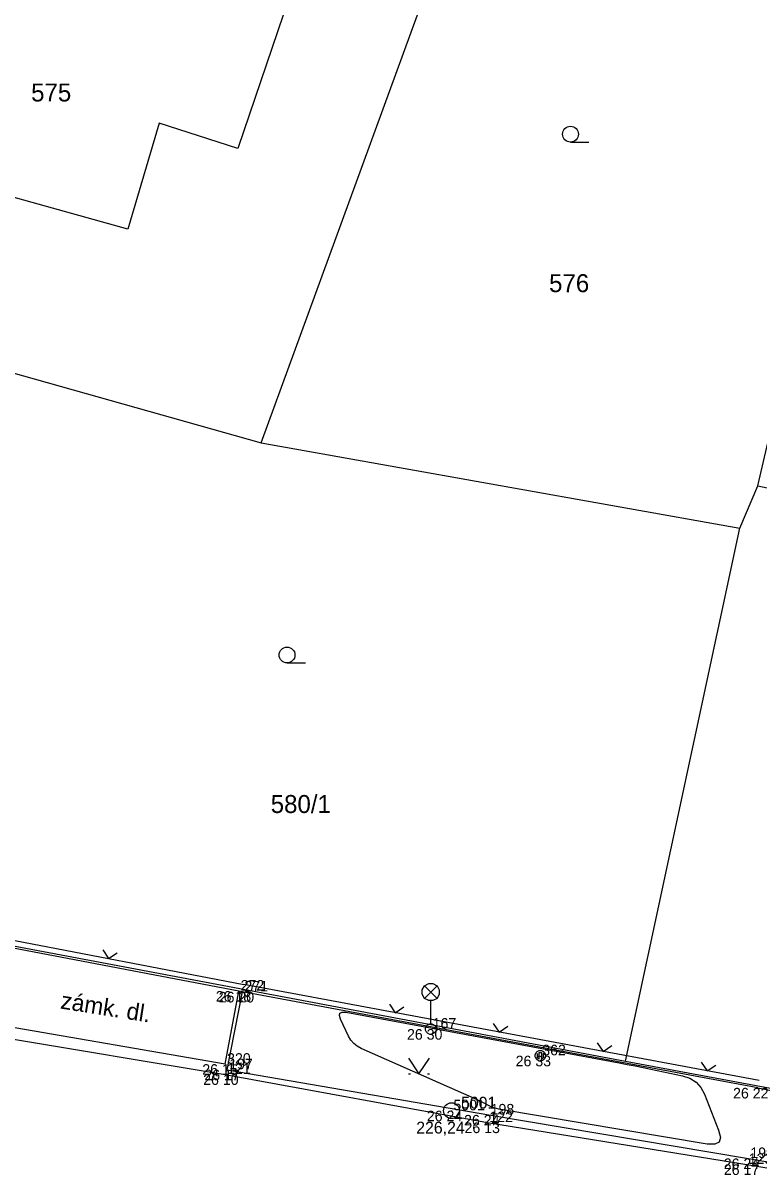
# Model space of a CAD drawing. Extents: x -702257 to -701487, y -1009871 to -1008841.
# Drawn here: x -701745.96 to -701728.56, y -1009385.88 to -1009358.61 of the extents above; entities that cross this region are included whole.
import ezdxf

# ---------------------------------------------------------------- set-up
doc = ezdxf.new("R2010")
doc.units = 0
for name, color, linetype in [('Ex_Minor Contours', 7, 'Continuous'), ('Z_bodove_pole', 7, 'Continuous'), ('Z_bodove_pole_cisla', 7, 'Continuous'), ('Z_bodove_pole_vysky', 7, 'Continuous'), ('Z_body', 7, 'Continuous'), ('Z_body_cisla', 7, 'Continuous'), ('Z_body_vysky_redukovane', 7, 'Continuous'), ('Z_katastr_cisla_pozemkova', 7, 'Continuous'), ('Z_katastr_cisla_stavebni', 7, 'Continuous'), ('Z_katastr_hranice', 7, 'Continuous'), ('Z_katastr_vnitrni_kresba', 7, 'Continuous'), ('Z_katastr_znacky_kultur', 7, 'Continuous'), ('Z_komunikace', 7, 'Continuous'), ('Z_obruba', 7, 'Continuous'), ('Z_ploty', 7, 'Continuous'), ('Z_ploty_znacky', 7, 'Continuous'), ('Z_popisy', 7, 'Continuous'), ('Z_rozhranni', 7, 'Continuous'), ('Z_site_vo_znaky', 7, 'Continuous'), ('Z_sloupy', 7, 'Continuous'), ('Z_znaky_kultur', 7, 'Continuous')]:
    doc.layers.add(name, color=color, linetype=linetype)

# ---------------------------------------------------------------- blocks, each defined once
blk = doc.blocks.new('Z34_1')
for p, q in [((-0.2, 0.925), (-0.15, 1.025)), ((-0.2, 0.825), (-0.2, 0.925)), ((-0.15, 0.725), (-0.2, 0.825)), ((-0.15, 1.025), (-0.05, 1.075)), ((0.15, 0.725), (-0.15, 1.025)), ((0.15, 1.025), (-0.15, 0.725)), ((-0.05, 1.075), (0.05, 1.075)), ((0.05, 1.075), (0.15, 1.025)), ((0.15, 1.025), (0.2, 0.925)), ((0.2, 0.825), (0.15, 0.725)), ((0.2, 0.925), (0.2, 0.825)), ((-0.05, 0.675), (-0.15, 0.725)), ((0.05, 0.675), (-0.05, 0.675)), ((0, 0.125), (0, 0.675)), ((0.15, 0.725), (0.05, 0.675)), ((-0.125, 0.025), (-0.1, 0.075)), ((-0.125, -0.025), (-0.125, 0.025)), ((-0.1, 0.075), (-0.075, 0.1)), ((-0.075, 0.1), (-0.025, 0.125)), ((-0.025, 0.125), (0.025, 0.125)), ((0.025, 0.125), (0.075, 0.1)), ((0.075, 0.1), (0.1, 0.075)), ((0.1, 0.075), (0.125, 0.025)), ((0.125, 0.025), (0.125, -0.025)), ((-0.1, -0.075), (-0.125, -0.025)), ((-0.075, -0.1), (-0.1, -0.075)), ((-0.025, -0.125), (-0.075, -0.1)), ((0.025, -0.125), (-0.025, -0.125)), ((0.075, -0.1), (0.025, -0.125)), ((0.1, -0.075), (0.075, -0.1)), ((0.125, -0.025), (0.1, -0.075))]:
    blk.add_line(p, q)
blk = doc.blocks.new('Z212_1')
for p, q in [((-0.175, 0.175), (0, 0)), ((0, 0), (0.175, 0.175))]:
    blk.add_line(p, q)
blk = doc.blocks.new('Z601_1')
for p, q in [((-0.125, 0.025), (-0.1, 0.075)), ((-0.125, -0.025), (-0.125, 0.025)), ((-0.1, 0.075), (-0.075, 0.1)), ((-0.075, 0.1), (-0.025, 0.125)), ((-0.075, 0.05), (-0.075, -0.05)), ((-0.025, 0.125), (0.025, 0.125)), ((-0.025, -0.075), (-0.025, 0.075)), ((-0.025, 0.075), (0.025, 0.075)), ((0.025, 0.125), (0.075, 0.1)), ((0.025, 0.075), (0.025, -0.075)), ((0.075, 0.1), (0.1, 0.075)), ((0.075, -0.05), (0.075, 0.05)), ((0.1, 0.075), (0.125, 0.025)), ((0.125, 0.025), (0.125, -0.025)), ((-0.1, -0.075), (-0.125, -0.025)), ((-0.075, -0.1), (-0.1, -0.075)), ((-0.075, -0.05), (-0.025, -0.075)), ((-0.025, -0.125), (-0.075, -0.1)), ((0.025, -0.125), (-0.025, -0.125)), ((0.025, -0.075), (0.075, -0.05)), ((0.075, -0.1), (0.025, -0.125)), ((0.1, -0.075), (0.075, -0.1)), ((0.125, -0.025), (0.1, -0.075))]:
    blk.add_line(p, q)
blk = doc.blocks.new('Z314_1')
for p, q in [((-0.25, 0.175), (0, -0.2)), ((0, -0.2), (0.25, 0.175)), ((-0.25, -0.2), (-0.2, -0.2)), ((0.2, -0.2), (0.25, -0.2))]:
    blk.add_line(p, q)
blk = doc.blocks.new('Z101')
for radius in [0.188, 0.0025]:
    blk.add_circle((0, 0), radius)
blk = doc.blocks.new('Z34_2')
for p, q in [((-0.2, 0.925), (-0.15, 1.025)), ((-0.2, 0.825), (-0.2, 0.925)), ((-0.15, 0.725), (-0.2, 0.825)), ((-0.15, 1.025), (-0.05, 1.075)), ((0.15, 0.725), (-0.15, 1.025)), ((0.15, 1.025), (-0.15, 0.725)), ((-0.05, 1.075), (0.05, 1.075)), ((0.05, 1.075), (0.15, 1.025)), ((0.15, 1.025), (0.2, 0.925)), ((0.2, 0.825), (0.15, 0.725)), ((0.2, 0.925), (0.2, 0.825)), ((-0.05, 0.675), (-0.15, 0.725)), ((0.05, 0.675), (-0.05, 0.675)), ((0, 0.125), (0, 0.675)), ((0.15, 0.725), (0.05, 0.675)), ((-0.125, 0.025), (-0.1, 0.075)), ((-0.125, -0.025), (-0.125, 0.025)), ((-0.1, 0.075), (-0.075, 0.1)), ((-0.075, 0.1), (-0.025, 0.125)), ((-0.025, 0.125), (0.025, 0.125)), ((0.025, 0.125), (0.075, 0.1)), ((0.075, 0.1), (0.1, 0.075)), ((0.1, 0.075), (0.125, 0.025)), ((0.125, 0.025), (0.125, -0.025)), ((-0.1, -0.075), (-0.125, -0.025)), ((-0.075, -0.1), (-0.1, -0.075)), ((-0.025, -0.125), (-0.075, -0.1)), ((0.025, -0.125), (-0.025, -0.125)), ((0.075, -0.1), (0.025, -0.125)), ((0.1, -0.075), (0.075, -0.1)), ((0.125, -0.025), (0.1, -0.075))]:
    blk.add_line(p, q)
blk = doc.blocks.new('Z601_2')
for p, q in [((-0.125, 0.025), (-0.1, 0.075)), ((-0.125, -0.025), (-0.125, 0.025)), ((-0.1, 0.075), (-0.075, 0.1)), ((-0.075, 0.1), (-0.025, 0.125)), ((-0.075, 0.05), (-0.075, -0.05)), ((-0.025, 0.125), (0.025, 0.125)), ((-0.025, -0.075), (-0.025, 0.075)), ((-0.025, 0.075), (0.025, 0.075)), ((0.025, 0.125), (0.075, 0.1)), ((0.025, 0.075), (0.025, -0.075)), ((0.075, 0.1), (0.1, 0.075)), ((0.075, -0.05), (0.075, 0.05)), ((0.1, 0.075), (0.125, 0.025)), ((0.125, 0.025), (0.125, -0.025)), ((-0.1, -0.075), (-0.125, -0.025)), ((-0.075, -0.1), (-0.1, -0.075)), ((-0.075, -0.05), (-0.025, -0.075)), ((-0.025, -0.125), (-0.075, -0.1)), ((0.025, -0.125), (-0.025, -0.125)), ((0.025, -0.075), (0.075, -0.05)), ((0.075, -0.1), (0.025, -0.125)), ((0.1, -0.075), (0.075, -0.1)), ((0.125, -0.025), (0.1, -0.075))]:
    blk.add_line(p, q)
blk = doc.blocks.new('POINT_DISPLAY')
blk.add_line((0, 0), (0, 0))

msp = doc.modelspace()

# ---------------------------------------------------------------- linework, layer by layer
at = {"layer": 'Ex_Minor Contours'}
msp.add_lwpolyline([(-701730.194, -1009383.571), (-701730.05, -1009383.662), (-701729.936, -1009383.788), (-701729.851, -1009383.948), (-701729.515, -1009384.798), (-701729.473, -1009384.97), (-701729.503, -1009385.082), (-701729.606, -1009385.135), (-701729.783, -1009385.129), (-701734.714, -1009384.301), (-701734.764, -1009384.291), (-701734.812, -1009384.277), (-701734.859, -1009384.26), (-701734.905, -1009384.239), (-701735.087, -1009384.147), (-701735.133, -1009384.125), (-701735.179, -1009384.103), (-701735.225, -1009384.081), (-701735.271, -1009384.061), (-701737.966, -1009382.869), (-701738.061, -1009382.817), (-701738.142, -1009382.751), (-701738.21, -1009382.671), (-701738.264, -1009382.577), (-701738.451, -1009382.172), (-701738.479, -1009382.086), (-701738.467, -1009382.031), (-701738.416, -1009382.006), (-701738.326, -1009382.011), (-701731.865, -1009383.209), (-701731.677, -1009383.244), (-701731.489, -1009383.281), (-701731.302, -1009383.319), (-701731.115, -1009383.357), (-701730.366, -1009383.514)], close=True, dxfattribs=at)
at = {"layer": 'Z_katastr_hranice'}
for p, q in [((-701740.33, -1009368.54), (-701736.21, -1009357.26)), ((-701728.59, -1009369.56), (-701725.71, -1009357.15)), ((-701751.41, -1009365.43), (-701740.33, -1009368.54)), ((-701740.33, -1009368.54), (-701729.01, -1009370.56)), ((-701729.01, -1009370.56), (-701728.59, -1009369.56)), ((-701728.59, -1009369.56), (-701728, -1009369.69)), ((-701731.72, -1009383.17), (-701729.01, -1009370.56)), ((-701754.74, -1009378.83), (-701731.72, -1009383.17)), ((-701731.72, -1009383.17), (-701725.19, -1009384.38))]:
    msp.add_line(p, q, dxfattribs=at)
at = {"layer": 'Z_katastr_vnitrni_kresba'}
for p, q in [((-701739.24, -1009356.73), (-701740.88, -1009361.58)), ((-701742.74, -1009360.98), (-701743.48, -1009363.49)), ((-701740.88, -1009361.58), (-701742.74, -1009360.98)), ((-701743.48, -1009363.49), (-701750.22, -1009361.61))]:
    msp.add_line(p, q, dxfattribs=at)
at = {"layer": 'Z_katastr_znacky_kultur'}
for p, q in [((-701733.018, -1009361.43), (-701732.581, -1009361.43)), ((-701739.718, -1009373.75), (-701739.281, -1009373.75))]:
    msp.add_line(p, q, dxfattribs=at)
for centre in [(-701733.018, -1009361.242), (-701739.718, -1009373.562)]:
    msp.add_circle(centre, 0.187, dxfattribs=at)
at = {"layer": 'Z_komunikace'}
for p, q in [((-701747.13, -1009382.49), (-701741.18, -1009383.48)), ((-701741.18, -1009383.48), (-701734.98, -1009384.62)), ((-701734.98, -1009384.62), (-701728.85, -1009385.61)), ((-701728.85, -1009385.61), (-701725.62, -1009386.16))]:
    msp.add_line(p, q, dxfattribs=at)
at = {"layer": 'Z_obruba'}
for p, q in [((-701741.13, -1009383.37), (-701740.77, -1009381.53)), ((-701741.13, -1009383.37), (-701734.95, -1009384.44)), ((-701734.95, -1009384.44), (-701728.81, -1009385.47)), ((-701728.81, -1009385.47), (-701726.48, -1009385.87))]:
    msp.add_line(p, q, dxfattribs=at)
at = {"layer": 'Z_ploty'}
for p, q in [((-701750.075, -1009379.561), (-701740.738, -1009381.358)), ((-701740.86, -1009381.51), (-701746.76, -1009380.39)), ((-701740.86, -1009381.51), (-701746.76, -1009380.39)), ((-701740.77, -1009381.53), (-701740.86, -1009381.51)), ((-701740.77, -1009381.53), (-701740.86, -1009381.51)), ((-701728.59, -1009383.8), (-701740.77, -1009381.53)), ((-701728.59, -1009383.8), (-701740.77, -1009381.53)), ((-701728.558, -1009383.628), (-701740.738, -1009381.358)), ((-701728.59, -1009383.8), (-701726.2, -1009384.27))]:
    msp.add_line(p, q, dxfattribs=at)
at = {"layer": 'Z_rozhranni'}
for q in [(-701740.86, -1009381.51), (-701740.86, -1009381.51), (-701747.08, -1009382.22), (-701747.08, -1009382.22)]:
    msp.add_line((-701741.18, -1009383.24), q, dxfattribs=at)

# ---------------------------------------------------------------- block references
at = {"layer": 'Z_bodove_pole'}
msp.add_blockref('Z101', (-701735.83, -1009384.34), dxfattribs=at)
msp.add_blockref('Z101', (-701735.83, -1009384.34), dxfattribs=at)
at = {"layer": 'Z_body'}
for p in [(-701740.86, -1009381.51), (-701740.77, -1009381.53), (-701736.32, -1009382.41), (-701741.18, -1009383.24), (-701733.73, -1009383.04), (-701741.18, -1009383.48), (-701741.13, -1009383.37), (-701728.59, -1009383.8), (-701735.83, -1009384.34), (-701734.98, -1009384.62), (-701734.95, -1009384.44), (-701728.85, -1009385.61), (-701728.81, -1009385.47)]:
    msp.add_blockref('POINT_DISPLAY', p, dxfattribs=at)
at = {"layer": 'Z_ploty_znacky'}
for p, rotation in [((-701743.938, -1009380.742), -10.899999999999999), ((-701737.16, -1009382.025), -10.600000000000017), ((-701734.702, -1009382.483), -10.600000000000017), ((-701732.244, -1009382.941), -10.600000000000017), ((-701729.787, -1009383.399), -10.600000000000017)]:
    msp.add_blockref('Z212_1', p, dxfattribs=dict(at, rotation=rotation))
at = {"layer": 'Z_site_vo_znaky'}
for name in ['Z34_1', 'Z34_2']:
    msp.add_blockref(name, (-701736.32, -1009382.41), dxfattribs=at)
at = {"layer": 'Z_sloupy'}
for name in ['Z601_1', 'Z601_2']:
    msp.add_blockref(name, (-701733.73, -1009383.04), dxfattribs=at)
at = {"layer": 'Z_znaky_kultur'}
msp.add_blockref('Z314_1', (-701736.6, -1009383.269), dxfattribs=at)

# ---------------------------------------------------------------- texts
at = {"layer": 'Z_bodove_pole_cisla'}
msp.add_text('5001', height=0.28, dxfattribs=at).set_placement((-701735.605, -1009384.29))
msp.add_text('5001', height=0.28, dxfattribs=at).set_placement((-701735.605, -1009384.29))
at = {"layer": 'Z_bodove_pole_vysky'}
msp.add_text('226,24', height=0.28, dxfattribs=at).set_placement((-701736.664, -1009384.881))
msp.add_text('226,24', height=0.28, dxfattribs=at).set_placement((-701736.664, -1009384.881))
at = {"layer": 'Z_body_cisla'}
for s, p in [('272', (-701740.815, -1009381.5)), ('271', (-701740.725, -1009381.52)), ('167', (-701736.275, -1009382.4)), ('320', (-701741.135, -1009383.23)), ('362', (-701733.685, -1009383.03)), ('121', (-701741.135, -1009383.47)), ('197', (-701741.085, -1009383.36)), ('5001', (-701735.785, -1009384.33)), ('198', (-701734.905, -1009384.43)), ('122', (-701734.935, -1009384.61)), ('123', (-701728.805, -1009385.6)), ('199', (-701728.765, -1009385.46))]:
    msp.add_text(s, height=0.25, dxfattribs=at).set_placement(p)
at = {"layer": 'Z_body_vysky_redukovane'}
for s, p in [('26 18', (-701741.402, -1009381.76)), ('26 20', (-701741.333, -1009381.78)), ('26 30', (-701736.882, -1009382.66)), ('26 15', (-701741.722, -1009383.49)), ('26 33', (-701734.313, -1009383.29)), ('26 10', (-701741.701, -1009383.73)), ('26 17', (-701741.672, -1009383.62)), ('26 22', (-701729.173, -1009384.05)), ('26 24', (-701736.413, -1009384.59)), ('26 24', (-701735.533, -1009384.69)), ('26 13', (-701735.522, -1009384.87)), ('26 24', (-701729.393, -1009385.72)), ('26 17', (-701729.392, -1009385.86))]:
    msp.add_text(s, height=0.25, dxfattribs=at).set_placement(p)
at = {"layer": 'Z_katastr_cisla_pozemkova'}
for s, p in [('576', (-701733.523, -1009364.98)), ('580/1', (-701740.104, -1009377.299))]:
    msp.add_text(s, height=0.425, dxfattribs=at).set_placement(p)
at = {"layer": 'Z_katastr_cisla_stavebni'}
msp.add_text('575', height=0.425, dxfattribs=at).set_placement((-701745.768, -1009360.47))
at = {"layer": 'Z_popisy'}
msp.add_text('zámk. dl.', height=0.4, rotation=351, dxfattribs=at).set_placement((-701745.091, -1009381.921))

doc.saveas('drawing.dxf')
